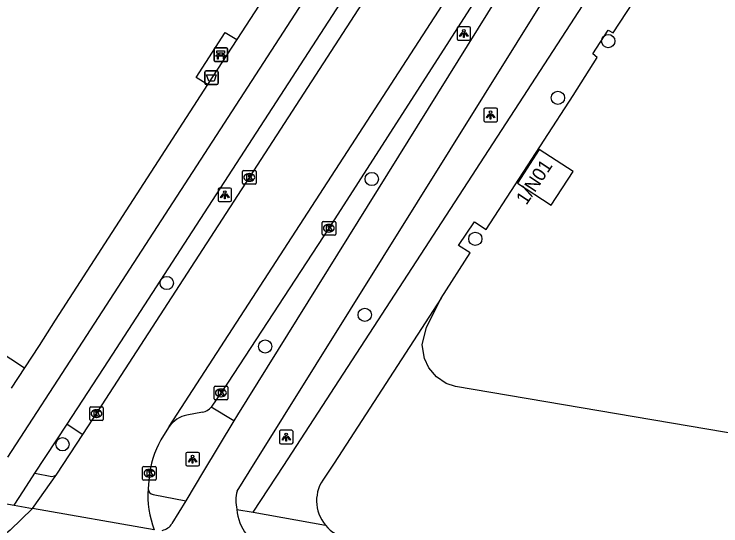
# Model space of a CAD drawing. Extents: x 161258 to 161838, y 380836 to 381727.
# Drawn here: x 161499.5 to 161551.5, y 380874.3 to 380912 of the extents above; entities that cross this region are included whole.
import ezdxf

# ---------------------------------------------------------------- set-up
doc = ezdxf.new("R2010")
doc.units = 0
for name, color, linetype in [('IMGEO_Afvalbak', 7, 'Continuous'), ('IMGEO_Bank', 7, 'Continuous'), ('IMGEO_Berm_open', 7, 'Continuous'), ('IMGEO_Boom', 7, 'Continuous'), ('IMGEO_Fietspad_gesloten', 7, 'Continuous'), ('IMGEO_Kolk', 7, 'Continuous'), ('IMGEO_Lichtpunt', 7, 'Continuous'), ('IMGEO_Loofbos', 7, 'Continuous'), ('IMGEO_Pand', 7, 'Continuous'), ('IMGEO_Pand_nummerreeks', 7, 'Continuous'), ('IMGEO_Parkeervlak_open', 7, 'Continuous'), ('IMGEO_Rijbaan_lokaal_gesloten', 7, 'Continuous'), ('IMGEO_Rijbaan_lokaal_open', 7, 'Continuous'), ('IMGEO_Voetpad_open', 7, 'Continuous')]:
    doc.layers.add(name, color=color, linetype=linetype)

msp = doc.modelspace()

# ---------------------------------------------------------------- linework, layer by layer
at = {"layer": 'IMGEO_Afvalbak'}
for p, q in [((161513.509, 380906.899), (161513.509, 380907.699)), ((161513.509, 380907.699), (161513.509, 380906.899)), ((161513.609, 380907.799), (161514.399, 380907.799)), ((161514.399, 380907.799), (161513.609, 380907.799)), ((161514.499, 380907.699), (161514.499, 380906.899)), ((161514.499, 380906.899), (161514.499, 380907.699)), ((161514.399, 380906.799), (161513.609, 380906.799)), ((161513.609, 380906.799), (161514.399, 380906.799))]:
    msp.add_line(p, q, dxfattribs=at)
msp.add_lwpolyline([(161513.652, 380907.513), (161514.356, 380907.513), (161514.207, 380907.043), (161513.801, 380907.043), (161513.652, 380907.513)], dxfattribs=at)
for centre, start, end in [((161513.609, 380907.699), 90, 180), ((161513.609, 380907.699), 90, 180), ((161514.399, 380907.699), 0, 90), ((161514.399, 380907.699), 360, 90), ((161513.609, 380906.899), 180, 270), ((161513.609, 380906.899), 180, 270), ((161514.399, 380906.899), 270, 0), ((161514.399, 380906.899), 270, 0)]:
    msp.add_arc(centre, 0.1, start, end, dxfattribs=at)
at = {"layer": 'IMGEO_Bank'}
for p, q in [((161514.196, 380908.562), (161514.196, 380909.403)), ((161514.196, 380909.403), (161514.196, 380908.562)), ((161514.271, 380909.487), (161515.112, 380909.487)), ((161515.112, 380909.487), (161514.271, 380909.487)), ((161515.196, 380909.412), (161515.196, 380908.571)), ((161515.196, 380908.571), (161515.196, 380909.412)), ((161514.893, 380908.885), (161514.5, 380908.885)), ((161514.505, 380908.993), (161514.505, 380909.099)), ((161514.549, 380909.099), (161514.549, 380908.993)), ((161514.837, 380909.105), (161514.555, 380909.105)), ((161514.555, 380908.987), (161514.837, 380908.987)), ((161514.843, 380908.993), (161514.843, 380909.099)), ((161514.887, 380909.099), (161514.887, 380908.993)), ((161515.121, 380908.487), (161514.28, 380908.487)), ((161514.28, 380908.487), (161515.121, 380908.487))]:
    msp.add_line(p, q, dxfattribs=at)
for points in [[(161514.499, 380909.105), (161514.413, 380909.105), (161514.413, 380909.266), (161514.976, 380909.266), (161514.976, 380909.105), (161514.893, 380909.105)], [(161514.443, 380908.885), (161514.301, 380908.885), (161514.413, 380908.987), (161514.499, 380908.987)], [(161514.493, 380908.878), (161514.493, 380908.671), (161514.45, 380908.671), (161514.45, 380908.878)], [(161514.893, 380908.987), (161514.976, 380908.987), (161515.088, 380908.885), (161514.949, 380908.885)], [(161514.943, 380908.878), (161514.943, 380908.671), (161514.899, 380908.671), (161514.899, 380908.878)]]:
    msp.add_lwpolyline(points, dxfattribs=at)
for centre, radius, start, end in [((161514.274, 380909.409), 0.0779, 92.4484, 184.2845), ((161514.274, 380909.409), 0.0779, 92.4484, 184.2845), ((161515.118, 380909.409), 0.0779, 2.4484, 94.2845), ((161515.118, 380909.409), 0.0779, 2.4484, 94.2845), ((161514.443, 380908.878), 0.00671, 2.8957, 87.1043), ((161514.5, 380908.878), 0.00671, 92.8957, 177.1043), ((161514.498, 380909.098), 0.00671, 2.8957, 87.1043), ((161514.498, 380908.994), 0.00671, 272.8957, 357.1043), ((161514.555, 380909.098), 0.00671, 92.8957, 177.1043), ((161514.555, 380908.994), 0.00671, 182.8957, 267.1043), ((161514.837, 380909.098), 0.00671, 2.8957, 87.1043), ((161514.837, 380908.994), 0.00671, 272.8957, 357.1043), ((161514.894, 380909.098), 0.00671, 92.8957, 177.1043), ((161514.894, 380908.994), 0.00671, 182.8957, 267.1043), ((161514.892, 380908.878), 0.00671, 2.8957, 87.1043), ((161514.949, 380908.878), 0.00671, 92.8957, 177.1043), ((161514.274, 380908.565), 0.0779, 182.4484, 274.2845), ((161514.274, 380908.565), 0.0779, 182.4484, 274.2845), ((161515.118, 380908.565), 0.0779, 272.4484, 4.2845), ((161515.118, 380908.565), 0.0779, 272.4484, 4.2845)]:
    msp.add_arc(centre, radius, start, end, dxfattribs=at)
at = {"layer": 'IMGEO_Berm_open'}
for points in [[(161515.665, 380882.025), (161513.994, 380883.019)], [(161503.381, 380881.765), (161504.523, 380881.003)]]:
    msp.add_lwpolyline(points, dxfattribs=at)
at = {"layer": 'IMGEO_Boom'}
for centre in [(161543.23, 380909.996), (161539.52, 380905.815), (161525.812, 380899.834), (161533.438, 380895.426), (161510.714, 380892.174), (161525.296, 380889.829), (161517.964, 380887.496), (161503.037, 380880.295)]:
    msp.add_circle(centre, 0.489, dxfattribs=at)
at = {"layer": 'IMGEO_Fietspad_gesloten'}
for points in [[(161581.633, 381006.84), (161581.562, 381006.731), (161578.938, 381002.688), (161504.207, 380887.394), (161498.991, 380879.345)], [(161503.381, 380881.765), (161506.413, 380886.439), (161550.334, 380954.192)], [(161515.901, 380876.852), (161516.774, 380878.276), (161548.922, 380929.776)], [(161544.685, 380928.722), (161515.927, 380882.459), (161515.665, 380882.025)], [(161500.997, 380878.155), (161503.381, 380881.765)], [(161515.665, 380882.025), (161513.423, 380878.315), (161512.107, 380876.132)], [(161499.475, 380875.817), (161500.162, 380876.872), (161500.997, 380878.155)], [(161493.75, 380876.843), (161499.475, 380875.817)], [(161512.107, 380876.132), (161511.097, 380874.45)], [(161499.475, 380875.817), (161500.831, 380875.559)]]:
    msp.add_lwpolyline(points, dxfattribs=at)
for centre, radius, start, end in [((161518.371, 380876.13), 2.573, 163.6962, 194.0955), ((161519.303, 380875.735), 3.436, 183.8772, 251.2929), ((161510.153, 380875.047), 1.117, 281.9457, 327.7033)]:
    msp.add_arc(centre, radius, start, end, dxfattribs=at)
at = {"layer": 'IMGEO_Kolk'}
for p, q in [((161516.288, 380899.528), (161516.288, 380900.38)), ((161516.363, 380900.454), (161517.215, 380900.454)), ((161517.289, 380900.38), (161517.289, 380899.528)), ((161516.776, 380900.234), (161516.801, 380900.234)), ((161517.215, 380899.454), (161516.363, 380899.454)), ((161516.799, 380899.674), (161516.774, 380899.674)), ((161522.227, 380896.707), (161523.079, 380896.707)), ((161522.152, 380895.781), (161522.152, 380896.633)), ((161522.64, 380896.487), (161522.665, 380896.487)), ((161523.153, 380896.633), (161523.153, 380895.781)), ((161523.079, 380895.707), (161522.227, 380895.707)), ((161522.663, 380895.927), (161522.638, 380895.927)), ((161514.201, 380883.652), (161514.201, 380884.504)), ((161514.276, 380884.578), (161515.128, 380884.578)), ((161514.689, 380884.358), (161514.714, 380884.358)), ((161515.202, 380884.504), (161515.202, 380883.652)), ((161514.712, 380883.798), (161514.687, 380883.798)), ((161515.128, 380883.578), (161514.276, 380883.578)), ((161505.038, 380882.127), (161505.038, 380882.979)), ((161505.113, 380883.053), (161505.965, 380883.053)), ((161505.526, 380882.833), (161505.551, 380882.833)), ((161506.039, 380882.979), (161506.039, 380882.127)), ((161505.549, 380882.273), (161505.524, 380882.273)), ((161505.965, 380882.053), (161505.113, 380882.053)), ((161508.938, 380877.737), (161508.938, 380878.589)), ((161509.013, 380878.663), (161509.865, 380878.663)), ((161509.426, 380878.443), (161509.451, 380878.443)), ((161509.939, 380878.589), (161509.939, 380877.737)), ((161509.865, 380877.663), (161509.013, 380877.663)), ((161509.449, 380877.883), (161509.424, 380877.883))]:
    msp.add_line(p, q, dxfattribs=at)
for points in [[(161516.288, 380899.528), (161516.288, 380900.38)], [(161516.363, 380900.454), (161517.215, 380900.454)], [(161517.289, 380900.38), (161517.289, 380899.528)], [(161516.609, 380900.154), (161516.732, 380900.154), (161516.732, 380900.003), (161516.862, 380900.154), (161517.026, 380900.154), (161516.88, 380900.003), (161517.033, 380899.754), (161516.881, 380899.754), (161516.796, 380899.918), (161516.732, 380899.851), (161516.732, 380899.754), (161516.609, 380899.754), (161516.609, 380900.154)], [(161517.215, 380899.454), (161516.363, 380899.454)], [(161522.227, 380896.707), (161523.079, 380896.707)], [(161522.152, 380895.781), (161522.152, 380896.633)], [(161522.473, 380896.407), (161522.596, 380896.407), (161522.596, 380896.256), (161522.726, 380896.407), (161522.89, 380896.407), (161522.744, 380896.256), (161522.897, 380896.007), (161522.745, 380896.007), (161522.66, 380896.171), (161522.596, 380896.104), (161522.596, 380896.007), (161522.473, 380896.007), (161522.473, 380896.407)], [(161523.153, 380896.633), (161523.153, 380895.781)], [(161523.079, 380895.707), (161522.227, 380895.707)], [(161514.201, 380883.652), (161514.201, 380884.504)], [(161514.276, 380884.578), (161515.128, 380884.578)], [(161514.522, 380884.278), (161514.645, 380884.278), (161514.645, 380884.127), (161514.775, 380884.278), (161514.939, 380884.278), (161514.793, 380884.127), (161514.946, 380883.878), (161514.794, 380883.878), (161514.709, 380884.042), (161514.645, 380883.975), (161514.645, 380883.878), (161514.522, 380883.878), (161514.522, 380884.278)], [(161515.202, 380884.504), (161515.202, 380883.652)], [(161515.128, 380883.578), (161514.276, 380883.578)], [(161505.038, 380882.127), (161505.038, 380882.979)], [(161505.113, 380883.053), (161505.965, 380883.053)], [(161505.359, 380882.753), (161505.482, 380882.753), (161505.482, 380882.602), (161505.612, 380882.753), (161505.776, 380882.753), (161505.63, 380882.602), (161505.783, 380882.353), (161505.631, 380882.353), (161505.546, 380882.517), (161505.482, 380882.45), (161505.482, 380882.353), (161505.359, 380882.353), (161505.359, 380882.753)], [(161506.039, 380882.979), (161506.039, 380882.127)], [(161505.965, 380882.053), (161505.113, 380882.053)], [(161508.938, 380877.737), (161508.938, 380878.589)], [(161509.013, 380878.663), (161509.865, 380878.663)], [(161509.939, 380878.589), (161509.939, 380877.737)], [(161509.259, 380878.363), (161509.382, 380878.363), (161509.382, 380878.212), (161509.512, 380878.363), (161509.676, 380878.363), (161509.53, 380878.212), (161509.683, 380877.963), (161509.531, 380877.963), (161509.446, 380878.127), (161509.382, 380878.06), (161509.382, 380877.963), (161509.259, 380877.963), (161509.259, 380878.363)], [(161509.865, 380877.663), (161509.013, 380877.663)]]:
    msp.add_lwpolyline(points, dxfattribs=at)
for centre, start, end in [((161516.365, 380900.378), 91.552, 178.448), ((161516.365, 380900.378), 91.552, 178.448), ((161517.213, 380900.378), 1.552, 88.448), ((161517.213, 380900.378), 1.552, 88.448), ((161516.365, 380899.53), 181.552, 268.448), ((161516.365, 380899.53), 181.552, 268.448), ((161517.213, 380899.53), 271.552, 358.448), ((161517.213, 380899.53), 271.552, 358.448), ((161522.229, 380896.631), 91.552, 178.448), ((161522.229, 380896.631), 91.552, 178.448), ((161523.077, 380896.631), 1.552, 88.448), ((161523.077, 380896.631), 1.552, 88.448), ((161522.229, 380895.783), 181.552, 268.448), ((161522.229, 380895.783), 181.552, 268.448), ((161523.077, 380895.783), 271.552, 358.448), ((161523.077, 380895.783), 271.552, 358.448), ((161514.278, 380884.502), 91.552, 178.448), ((161514.278, 380884.502), 91.552, 178.448), ((161515.126, 380884.502), 1.552, 88.448), ((161515.126, 380884.502), 1.552, 88.448), ((161514.278, 380883.654), 181.552, 268.448), ((161514.278, 380883.654), 181.552, 268.448), ((161515.126, 380883.654), 271.552, 358.448), ((161515.126, 380883.654), 271.552, 358.448), ((161505.115, 380882.977), 91.552, 178.448), ((161505.115, 380882.977), 91.552, 178.448), ((161505.963, 380882.977), 1.552, 88.448), ((161505.963, 380882.977), 1.552, 88.448), ((161505.115, 380882.129), 181.552, 268.448), ((161505.115, 380882.129), 181.552, 268.448), ((161505.963, 380882.129), 271.552, 358.448), ((161505.963, 380882.129), 271.552, 358.448), ((161509.015, 380878.587), 91.552, 178.448), ((161509.015, 380878.587), 91.552, 178.448), ((161509.863, 380878.587), 1.552, 88.448), ((161509.863, 380878.587), 1.552, 88.448), ((161509.015, 380877.739), 181.552, 268.448), ((161509.015, 380877.739), 181.552, 268.448), ((161509.863, 380877.739), 271.552, 358.448), ((161509.863, 380877.739), 271.552, 358.448)]:
    msp.add_arc(centre, 0.0765, start, end, dxfattribs=at)
for centre, major_axis, ratio, start_param, end_param in [((161516.775, 380899.954), (-0.387, 0.002), 0.722429, 4.712389, 7.853982), ((161516.8, 380899.954), (-0.39, 0.002), 0.717154, 1.570796, 4.712389), ((161522.639, 380896.207), (-0.387, 0.002), 0.722429, 4.712389, 7.853982), ((161522.664, 380896.207), (-0.39, 0.002), 0.717154, 1.570796, 4.712389), ((161514.688, 380884.078), (-0.387, 0.002), 0.722429, 4.712389, 7.853982), ((161514.713, 380884.078), (-0.39, 0.002), 0.717154, 1.570796, 4.712389), ((161505.525, 380882.553), (-0.387, 0.002), 0.722429, 4.712389, 7.853982), ((161505.55, 380882.553), (-0.39, 0.002), 0.717154, 1.570796, 4.712389), ((161509.425, 380878.163), (-0.387, 0.002), 0.722429, 4.712389, 7.853982), ((161509.45, 380878.163), (-0.39, 0.002), 0.717154, 1.570796, 4.712389)]:
    msp.add_ellipse(centre, major_axis=major_axis, ratio=ratio, start_param=start_param, end_param=end_param, dxfattribs=at)
at = {"layer": 'IMGEO_Lichtpunt'}
for p, q in [((161532.09, 380910.954), (161532.09, 380910.147)), ((161532.09, 380910.954), (161532.09, 380910.147)), ((161532.992, 380911.049), (161532.184, 380911.049)), ((161532.992, 380911.049), (161532.184, 380911.049)), ((161533.086, 380910.147), (161533.086, 380910.954)), ((161533.086, 380910.147), (161533.086, 380910.954)), ((161532.184, 380910.053), (161532.992, 380910.053)), ((161532.184, 380910.053), (161532.992, 380910.053)), ((161534.968, 380905.053), (161534.16, 380905.053)), ((161534.968, 380905.053), (161534.16, 380905.053)), ((161534.066, 380904.958), (161534.066, 380904.151)), ((161534.066, 380904.958), (161534.066, 380904.151)), ((161535.062, 380904.151), (161535.062, 380904.958)), ((161535.062, 380904.151), (161535.062, 380904.958)), ((161534.16, 380904.057), (161534.968, 380904.057)), ((161534.16, 380904.057), (161534.968, 380904.057)), ((161514.489, 380899.076), (161514.489, 380898.269)), ((161514.489, 380899.076), (161514.489, 380898.269)), ((161515.391, 380899.171), (161514.583, 380899.171)), ((161515.391, 380899.171), (161514.583, 380899.171)), ((161515.485, 380898.269), (161515.485, 380899.076)), ((161515.485, 380898.269), (161515.485, 380899.076)), ((161514.583, 380898.175), (161515.391, 380898.175)), ((161514.583, 380898.175), (161515.391, 380898.175)), ((161519.017, 380881.228), (161519.017, 380880.421)), ((161519.017, 380881.228), (161519.017, 380880.421)), ((161519.919, 380881.323), (161519.111, 380881.323)), ((161519.919, 380881.323), (161519.111, 380881.323)), ((161520.013, 380880.421), (161520.013, 380881.228)), ((161520.013, 380880.421), (161520.013, 380881.228)), ((161519.111, 380880.327), (161519.919, 380880.327)), ((161519.111, 380880.327), (161519.919, 380880.327)), ((161512.119, 380879.605), (161512.119, 380878.798)), ((161512.119, 380879.605), (161512.119, 380878.798)), ((161513.021, 380879.7), (161512.213, 380879.7)), ((161513.021, 380879.7), (161512.213, 380879.7)), ((161513.115, 380878.798), (161513.115, 380879.605)), ((161513.115, 380878.798), (161513.115, 380879.605)), ((161512.213, 380878.704), (161513.021, 380878.704)), ((161512.213, 380878.704), (161513.021, 380878.704))]:
    msp.add_line(p, q, dxfattribs=at)
for points in [[(161532.464, 380910.618), (161532.503, 380910.59), (161532.315, 380910.328), (161532.277, 380910.355), (161532.464, 380910.618)], [(161532.566, 380910.57), (161532.613, 380910.57), (161532.613, 380910.248), (161532.566, 380910.248), (161532.566, 380910.57)], [(161532.676, 380910.59), (161532.714, 380910.617), (161532.901, 380910.355), (161532.862, 380910.327), (161532.676, 380910.59)], [(161534.44, 380904.622), (161534.479, 380904.594), (161534.291, 380904.332), (161534.253, 380904.359), (161534.44, 380904.622)], [(161534.542, 380904.574), (161534.589, 380904.574), (161534.589, 380904.252), (161534.542, 380904.252), (161534.542, 380904.574)], [(161534.652, 380904.594), (161534.69, 380904.621), (161534.877, 380904.359), (161534.838, 380904.331), (161534.652, 380904.594)], [(161514.863, 380898.74), (161514.902, 380898.712), (161514.714, 380898.45), (161514.676, 380898.477), (161514.863, 380898.74)], [(161515.075, 380898.712), (161515.113, 380898.739), (161515.3, 380898.477), (161515.261, 380898.449), (161515.075, 380898.712)], [(161514.965, 380898.692), (161515.012, 380898.692), (161515.012, 380898.37), (161514.965, 380898.37), (161514.965, 380898.692)], [(161519.391, 380880.892), (161519.43, 380880.864), (161519.242, 380880.602), (161519.204, 380880.629), (161519.391, 380880.892)], [(161519.493, 380880.844), (161519.54, 380880.844), (161519.54, 380880.522), (161519.493, 380880.522), (161519.493, 380880.844)], [(161519.603, 380880.864), (161519.641, 380880.891), (161519.828, 380880.629), (161519.789, 380880.601), (161519.603, 380880.864)], [(161512.493, 380879.269), (161512.532, 380879.241), (161512.344, 380878.979), (161512.306, 380879.006), (161512.493, 380879.269)], [(161512.595, 380879.221), (161512.642, 380879.221), (161512.642, 380878.899), (161512.595, 380878.899), (161512.595, 380879.221)], [(161512.705, 380879.241), (161512.743, 380879.268), (161512.93, 380879.006), (161512.891, 380878.978), (161512.705, 380879.241)]]:
    msp.add_lwpolyline(points, dxfattribs=at)
for centre in [(161532.589, 380910.752), (161534.565, 380904.756), (161514.988, 380898.874), (161519.516, 380881.026), (161512.618, 380879.403)]:
    msp.add_circle(centre, 0.0994, dxfattribs=at)
for centre, start, end in [((161532.184, 380910.954), 90, 180), ((161532.184, 380910.954), 90, 180), ((161532.992, 380910.954), 0, 90), ((161532.992, 380910.954), 0, 90), ((161532.184, 380910.147), 180, 270), ((161532.184, 380910.147), 180, 270), ((161532.992, 380910.147), 270, 0), ((161532.992, 380910.147), 270, 360), ((161534.16, 380904.958), 90, 180), ((161534.16, 380904.958), 90, 180), ((161534.968, 380904.958), 0, 90), ((161534.968, 380904.958), 0, 90), ((161534.16, 380904.151), 180, 270), ((161534.16, 380904.151), 180, 270), ((161534.968, 380904.151), 270, 0), ((161534.968, 380904.151), 270, 360), ((161514.583, 380899.076), 90, 180), ((161514.583, 380899.076), 90, 180), ((161515.391, 380899.076), 0, 90), ((161515.391, 380899.076), 0, 90), ((161514.583, 380898.269), 180, 270), ((161514.583, 380898.269), 180, 270), ((161515.391, 380898.269), 270, 0), ((161515.391, 380898.269), 270, 360), ((161519.111, 380881.228), 90, 180), ((161519.111, 380881.228), 90, 180), ((161519.919, 380881.228), 0, 90), ((161519.919, 380881.228), 0, 90), ((161519.111, 380880.421), 180, 270), ((161519.111, 380880.421), 180, 270), ((161519.919, 380880.421), 270, 0), ((161519.919, 380880.421), 270, 360), ((161512.213, 380879.605), 90, 180), ((161512.213, 380879.605), 90, 180), ((161513.021, 380879.605), 0, 90), ((161513.021, 380879.605), 0, 90), ((161512.213, 380878.798), 180, 270), ((161512.213, 380878.798), 180, 270), ((161513.021, 380878.798), 270, 0), ((161513.021, 380878.798), 270, 360)]:
    msp.add_arc(centre, 0.0946, start, end, dxfattribs=at)
at = {"layer": 'IMGEO_Loofbos'}
msp.add_lwpolyline([(161635.09, 380867.033), (161531.988, 380884.543), (161531.3, 380884.776), (161530.573, 380885.257), (161530.003, 380885.931), (161529.683, 380886.616), (161529.531, 380887.614), (161529.831, 380888.91), (161530.918, 380891.057)], dxfattribs=at)
at = {"layer": 'IMGEO_Pand'}
msp.add_lwpolyline([(161539.026, 380897.897), (161540.639, 380900.399), (161538.15, 380902.004), (161536.533, 380899.52), (161539.026, 380897.897)], dxfattribs=at)
at = {"layer": 'IMGEO_Parkeervlak_open'}
for points in [[(161543.938, 380929.207), (161533.683, 380913.408), (161522.653, 380896.207), (161515.229, 380884.867), (161513.994, 380883.019)], [(161513.356, 380882.654), (161512.202, 380882.451)]]:
    msp.add_lwpolyline(points, dxfattribs=at)
for centre, radius, start, end in [((161513.037, 380883.952), 1.336, 283.8088, 315.739), ((161512.682, 380880.278), 2.226, 102.4631, 143.6797)]:
    msp.add_arc(centre, radius, start, end, dxfattribs=at)
at = {"layer": 'IMGEO_Rijbaan_lokaal_gesloten'}
for points in [[(161500.831, 380875.559), (161499.175, 380873.962), (161497.056, 380872.257)], [(161509.795, 380873.992), (161500.831, 380875.559)]]:
    msp.add_lwpolyline(points, dxfattribs=at)
at = {"layer": 'IMGEO_Rijbaan_lokaal_open'}
for points in [[(161504.523, 380881.003), (161505.64, 380882.718), (161544.901, 380943.304)], [(161510.889, 380881.596), (161543.871, 380932.477)], [(161510.889, 380881.596), (161510.462, 380880.94)], [(161502.618, 380878.101), (161504.523, 380881.003)], [(161500.831, 380875.559), (161502.618, 380878.101)], [(161509.439, 380878.163), (161509.332, 380877.038)]]:
    msp.add_lwpolyline(points, dxfattribs=at)
for centre, radius, start, end in [((161516.644, 380877.086), 7.285, 148.0576, 171.4966), ((161516.448, 380876.561), 7.132, 176.1683, 201.1176)]:
    msp.add_arc(centre, radius, start, end, dxfattribs=at)
at = {"layer": 'IMGEO_Voetpad_open'}
for points in [[(161578.923, 381007.348), (161578.828, 381007.201), (161576.218, 381003.146), (161558.236, 380975.49), (161556.737, 380973.185), (161556.123, 380972.241), (161554.834, 380970.332), (161546.174, 380956.722), (161540.302, 380947.69), (161515.878, 380910.106)], [(161530.918, 380891.057), (161533.069, 380894.385), (161532.197, 380894.942), (161533.387, 380896.677), (161534.24, 380896.125), (161540.643, 380905.976), (161542.416, 380908.796), (161542.1, 380909.047), (161543.218, 380910.801), (161543.578, 380910.592), (161547.061, 380915.899), (161546.55, 380916.226), (161547.209, 380917.209), (161547.753, 380916.964), (161553.165, 380925.238), (161553.779, 380926.192), (161556.537, 380930.473), (161579.588, 380966.248), (161580.753, 380968.057)], [(161517.075, 380875.292), (161519.332, 380878.728), (161551.434, 380928.192), (161548.922, 380929.776)], [(161513.725, 380906.807), (161512.888, 380907.32), (161515.02, 380910.631), (161515.878, 380910.106)], [(161515.878, 380910.106), (161513.725, 380906.807)], [(161513.725, 380906.807), (161502.49, 380889.425), (161501.31, 380887.571), (161500.227, 380885.918)], [(161530.918, 380891.057), (161523.047, 380878.902), (161522.349, 380877.864)], [(161494.323, 380889.817), (161500.227, 380885.918)], [(161500.227, 380885.918), (161499.245, 380884.419)], [(161500.997, 380878.155), (161502.242, 380877.925)], [(161509.724, 380876.591), (161512.107, 380876.132)], [(161515.875, 380875.503), (161517.075, 380875.292)], [(161517.075, 380875.292), (161522.407, 380874.328)]]:
    msp.add_lwpolyline(points, dxfattribs=at)
for centre, radius, start, end in [((161502.237, 380878.424), 0.499, 270.5209, 319.6463), ((161524.538, 380876.131), 2.792, 141.636, 220.2435), ((161509.788, 380877.043), 0.456, 180.5672, 261.9316), ((161524.535, 380876.125), 2.785, 220.1883, 260.6686)]:
    msp.add_arc(centre, radius, start, end, dxfattribs=at)

# ---------------------------------------------------------------- texts
at = {"layer": 'IMGEO_Pand_nummerreeks'}
msp.add_text('1/N01', height=1, rotation=56.464, dxfattribs=at).set_placement((161537.198, 380897.859))

doc.saveas('drawing.dxf')
